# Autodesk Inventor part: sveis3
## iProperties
Created: 2009-09
Part Number: sveis3
Document SubType Name: Modeling
Designer: TB
Mass: 49.3696 g
Surface Area: 137.015 cm^2
Volume: 49.3696 cm^3
Density: 1 g/cm^3
Author: TB
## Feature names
1. Extrusion1
2. Revolution1
3. Extrusion2
